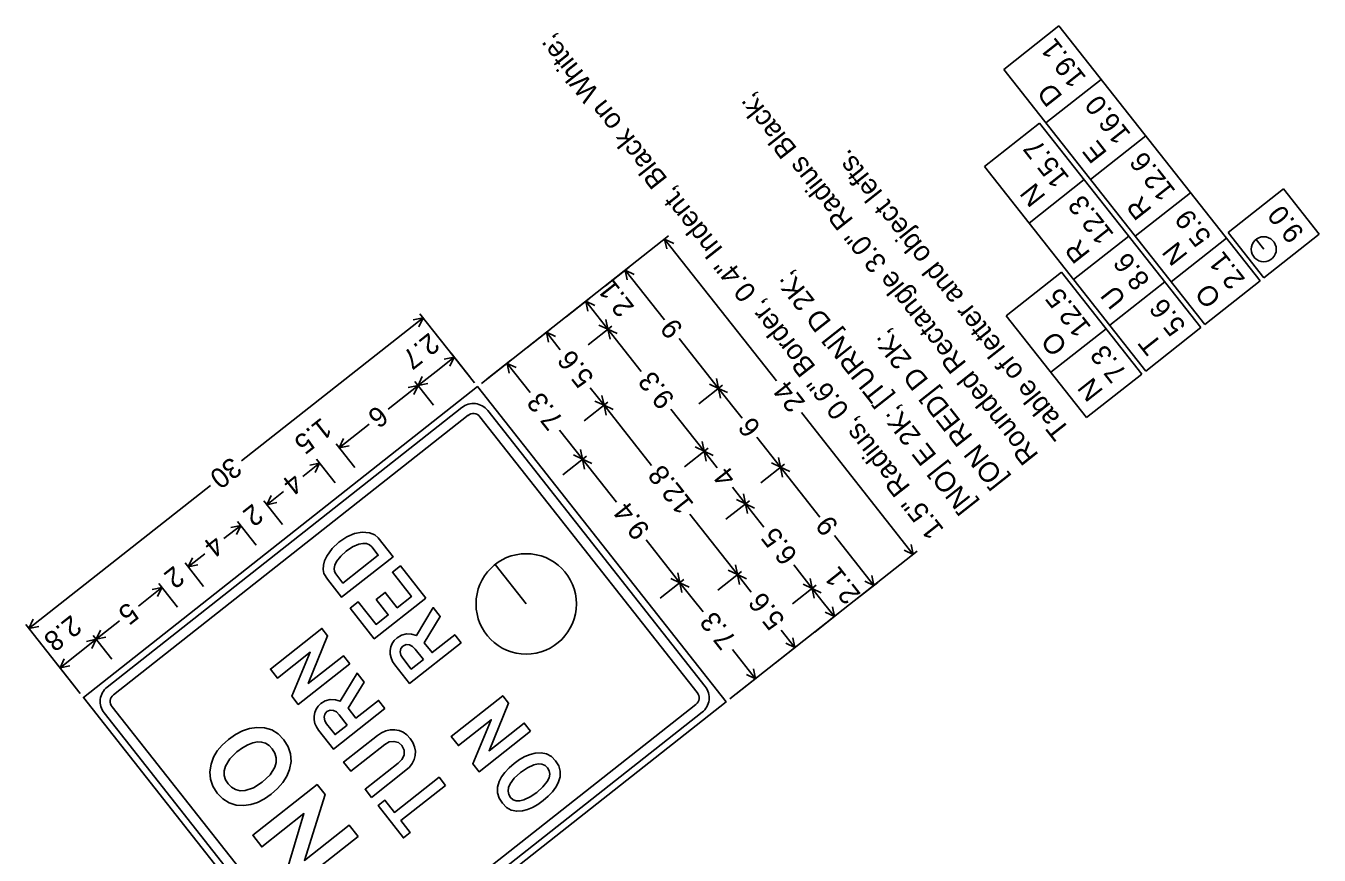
# Model space of a CAD drawing. Extents: x 672239 to 673995, y 1673540 to 1675195.
# Drawn here: x 672638.7 to 672697.6, y 1674762.7 to 1674800.5 of the extents above; entities that cross this region are included whole.
import ezdxf

# ---------------------------------------------------------------- set-up
doc = ezdxf.new("R2010")
doc.units = 0
doc.layers.add('C-ALGN-LINE', color=7, linetype='Continuous')

msp = doc.modelspace()

# ---------------------------------------------------------------- linework, layer by layer
at = {"layer": 'C-ALGN-LINE'}
for p, q in [((672683.213, 1674798.474), (672685.726, 1674800.455)), ((672685.726, 1674800.455), (672694.885, 1674788.838)), ((672683.213, 1674798.474), (672692.371, 1674786.856)), ((672685.134, 1674796.037), (672687.647, 1674798.019)), ((672682.334, 1674794.05), (672684.847, 1674796.031)), ((672684.847, 1674796.031), (672692.192, 1674786.715)), ((672687.164, 1674793.462), (672689.677, 1674795.444)), ((672682.334, 1674794.05), (672689.679, 1674784.733)), ((672684.364, 1674791.475), (672686.878, 1674793.456)), ((672689.203, 1674790.875), (672691.716, 1674792.857)), ((672693.434, 1674791.047), (672695.948, 1674793.028)), ((672695.948, 1674793.028), (672697.578, 1674790.961)), ((672667.944, 1674790.887), (672659.417, 1674784.164)), ((672672.861, 1674784.281), (672667.765, 1674790.745)), ((672668.179, 1674790.55), (672667.765, 1674790.745)), ((672667.857, 1674790.297), (672667.765, 1674790.745)), ((672686.395, 1674788.899), (672688.908, 1674790.88)), ((672690.839, 1674788.8), (672693.353, 1674790.781)), ((672693.434, 1674791.047), (672695.064, 1674788.979)), ((672694.702, 1674790.731), (672695.056, 1674790.282)), ((672695.056, 1674790.282), (672694.702, 1674790.731)), ((672695.064, 1674788.979), (672697.578, 1674790.961)), ((672666.149, 1674789.471), (672665.072, 1674788.622)), ((672667.758, 1674787.061), (672665.969, 1674789.33)), ((672666.383, 1674789.135), (672665.969, 1674789.33)), ((672666.062, 1674788.882), (672665.969, 1674789.33)), ((672683.325, 1674787.254), (672685.839, 1674789.235)), ((672685.839, 1674789.235), (672689.499, 1674784.592)), ((672688.036, 1674786.817), (672690.55, 1674788.798)), ((672692.371, 1674786.856), (672694.885, 1674788.838)), ((672664.354, 1674788.056), (672663.277, 1674787.207)), ((672664.679, 1674787.274), (672664.174, 1674787.915)), ((672664.588, 1674787.72), (672664.174, 1674787.915)), ((672664.267, 1674787.467), (672664.174, 1674787.915)), ((672648.494, 1674780.647), (672656.761, 1674787.164)), ((672656.313, 1674787.071), (672656.761, 1674787.164)), ((672656.566, 1674786.751), (672656.761, 1674787.164)), ((672656.619, 1674787.344), (672659.096, 1674784.202)), ((672664.679, 1674787.274), (672665.184, 1674786.634)), ((672665.091, 1674787.082), (672665.184, 1674786.634)), ((672683.325, 1674787.254), (672686.986, 1674782.611)), ((672662.559, 1674786.641), (672661.481, 1674785.792)), ((672663.011, 1674785.698), (672662.379, 1674786.499)), ((672662.793, 1674786.304), (672662.379, 1674786.499)), ((672662.472, 1674786.052), (672662.379, 1674786.499)), ((672665.363, 1674786.776), (672664.286, 1674785.926)), ((672665.363, 1674786.776), (672664.286, 1674785.926)), ((672664.77, 1674786.829), (672665.184, 1674786.634)), ((672666.699, 1674784.712), (672665.184, 1674786.634)), ((672665.598, 1674786.439), (672665.184, 1674786.634)), ((672665.277, 1674786.186), (672665.184, 1674786.634)), ((672685.359, 1674784.675), (672687.872, 1674786.656)), ((672689.679, 1674784.733), (672692.192, 1674786.715)), ((672668.426, 1674786.213), (672670.215, 1674783.944)), ((672657.353, 1674784.72), (672658.176, 1674785.369)), ((672657.728, 1674785.276), (672658.176, 1674785.369)), ((672657.981, 1674784.955), (672658.176, 1674785.369)), ((672658.034, 1674785.549), (672658.884, 1674784.471)), ((672660.763, 1674785.226), (672659.686, 1674784.376)), ((672657.353, 1674784.72), (672656.53, 1674784.072)), ((672661.633, 1674783.753), (672660.584, 1674785.084)), ((672660.998, 1674784.889), (672660.584, 1674785.084)), ((672660.677, 1674784.636), (672660.584, 1674785.084)), ((672655.167, 1674782.997), (672656.53, 1674784.072)), ((672656.083, 1674783.979), (672656.53, 1674784.072)), ((672656.335, 1674783.658), (672656.53, 1674784.072)), ((672656.389, 1674784.251), (672657.238, 1674783.174)), ((672656.389, 1674784.251), (672657.238, 1674783.174)), ((672656.725, 1674784.485), (672656.53, 1674784.072)), ((672656.978, 1674784.165), (672656.53, 1674784.072)), ((672670.395, 1674784.086), (672669.318, 1674783.237)), ((672670.395, 1674784.086), (672669.318, 1674783.237)), ((672669.801, 1674784.139), (672670.215, 1674783.944)), ((672670.122, 1674784.392), (672670.215, 1674783.944)), ((672686.986, 1674782.611), (672689.499, 1674784.592)), ((672664.37, 1674783.974), (672665.002, 1674783.172)), ((672664.909, 1674783.62), (672665.002, 1674783.172)), ((672671.29, 1674782.58), (672670.215, 1674783.944)), ((672670.629, 1674783.749), (672670.215, 1674783.944)), ((672670.308, 1674783.496), (672670.215, 1674783.944)), ((672665.182, 1674783.314), (672664.104, 1674782.465)), ((672665.182, 1674783.314), (672664.104, 1674782.465)), ((672664.588, 1674783.367), (672665.002, 1674783.172)), ((672667.165, 1674780.429), (672665.002, 1674783.172)), ((672665.416, 1674782.977), (672665.002, 1674783.172)), ((672665.095, 1674782.724), (672665.002, 1674783.172)), ((672668.046, 1674783.003), (672669.562, 1674781.081)), ((672673.991, 1674782.847), (672679.087, 1674776.383)), ((672654.304, 1674782.316), (672652.94, 1674781.241)), ((672662.978, 1674782.047), (672664.028, 1674780.716)), ((672671.971, 1674781.718), (672673.046, 1674780.354)), ((672652.798, 1674781.421), (672653.648, 1674780.344)), ((672653.135, 1674781.655), (672652.94, 1674781.241)), ((672653.388, 1674781.334), (672652.94, 1674781.241)), ((672663.935, 1674781.164), (672664.028, 1674780.716)), ((672669.741, 1674781.222), (672668.664, 1674780.373)), ((672669.148, 1674781.276), (672669.562, 1674781.081)), ((672669.469, 1674781.529), (672669.562, 1674781.081)), ((672670.161, 1674780.321), (672669.562, 1674781.081)), ((672669.976, 1674780.886), (672669.562, 1674781.081)), ((672669.654, 1674780.633), (672669.562, 1674781.081)), ((672651.282, 1674779.934), (672652.042, 1674780.534)), ((672651.595, 1674780.441), (672652.042, 1674780.534)), ((672651.847, 1674780.12), (672652.042, 1674780.534)), ((672651.901, 1674780.713), (672652.75, 1674779.636)), ((672664.207, 1674780.857), (672663.13, 1674780.008)), ((672664.207, 1674780.857), (672663.13, 1674780.008)), ((672663.614, 1674780.911), (672664.028, 1674780.716)), ((672665.571, 1674778.758), (672664.028, 1674780.716)), ((672664.441, 1674780.521), (672664.028, 1674780.716)), ((672664.121, 1674780.268), (672664.028, 1674780.716)), ((672673.225, 1674780.495), (672672.148, 1674779.646)), ((672672.632, 1674780.549), (672673.046, 1674780.354)), ((672672.953, 1674780.802), (672673.046, 1674780.354)), ((672674.835, 1674778.085), (672673.046, 1674780.354)), ((672673.46, 1674780.159), (672673.046, 1674780.354)), ((672673.139, 1674779.906), (672673.046, 1674780.354)), ((672647.075, 1674779.528), (672638.808, 1674773.012)), ((672670.85, 1674779.447), (672671.449, 1674778.687)), ((672649.507, 1674778.826), (672650.356, 1674777.749)), ((672650.409, 1674779.246), (672649.649, 1674778.647)), ((672649.844, 1674779.06), (672649.649, 1674778.647)), ((672650.096, 1674778.74), (672649.649, 1674778.647)), ((672671.628, 1674778.829), (672670.551, 1674777.98)), ((672671.035, 1674778.882), (672671.449, 1674778.687)), ((672671.356, 1674779.135), (672671.449, 1674778.687)), ((672668.915, 1674778.208), (672671.078, 1674775.465)), ((672672.29, 1674777.62), (672671.449, 1674778.687)), ((672671.863, 1674778.492), (672671.449, 1674778.687)), ((672671.542, 1674778.239), (672671.449, 1674778.687)), ((672647.692, 1674777.104), (672648.452, 1674777.703)), ((672648.004, 1674777.61), (672648.452, 1674777.703)), ((672648.257, 1674777.289), (672648.452, 1674777.703)), ((672648.31, 1674777.883), (672649.159, 1674776.805)), ((672666.919, 1674777.049), (672668.462, 1674775.091)), ((672675.503, 1674777.237), (672677.292, 1674774.968)), ((672646.818, 1674776.415), (672646.058, 1674775.816)), ((672679.266, 1674776.525), (672670.739, 1674769.802)), ((672678.673, 1674776.578), (672679.087, 1674776.383)), ((672678.994, 1674776.831), (672679.087, 1674776.383)), ((672645.917, 1674775.996), (672646.766, 1674774.918)), ((672646.253, 1674776.23), (672646.058, 1674775.816)), ((672646.506, 1674775.909), (672646.058, 1674775.816)), ((672660.042, 1674775.924), (672661.458, 1674774.129)), ((672661.458, 1674774.129), (672660.042, 1674775.924)), ((672670.985, 1674775.913), (672671.078, 1674775.465)), ((672673.646, 1674775.9), (672674.487, 1674774.833)), ((672668.642, 1674775.232), (672667.565, 1674774.383)), ((672668.048, 1674775.286), (672668.462, 1674775.091)), ((672668.369, 1674775.539), (672668.462, 1674775.091)), ((672671.258, 1674775.606), (672670.181, 1674774.757)), ((672670.665, 1674775.66), (672671.078, 1674775.465)), ((672671.71, 1674774.663), (672671.078, 1674775.465)), ((672671.492, 1674775.27), (672671.078, 1674775.465)), ((672671.171, 1674775.017), (672671.078, 1674775.465)), ((672674.394, 1674775.281), (672674.487, 1674774.833)), ((672677.199, 1674775.416), (672677.292, 1674774.968)), ((672643.791, 1674774.029), (672644.861, 1674774.873)), ((672644.414, 1674774.78), (672644.861, 1674774.873)), ((672644.666, 1674774.459), (672644.861, 1674774.873)), ((672644.72, 1674775.052), (672645.569, 1674773.975)), ((672669.512, 1674773.759), (672668.462, 1674775.091)), ((672668.876, 1674774.896), (672668.462, 1674775.091)), ((672668.555, 1674774.643), (672668.462, 1674775.091)), ((672674.666, 1674774.975), (672673.589, 1674774.126)), ((672674.073, 1674775.028), (672674.487, 1674774.833)), ((672674.992, 1674774.193), (672674.487, 1674774.833)), ((672674.901, 1674774.639), (672674.487, 1674774.833)), ((672674.58, 1674774.386), (672674.487, 1674774.833)), ((672677.471, 1674775.11), (672676.394, 1674774.261)), ((672676.878, 1674775.163), (672677.292, 1674774.968)), ((672674.992, 1674774.193), (672675.496, 1674773.553)), ((672675.404, 1674774.001), (672675.496, 1674773.553)), ((672639.003, 1674773.425), (672638.808, 1674773.012)), ((672675.676, 1674773.694), (672674.599, 1674772.845)), ((672675.083, 1674773.748), (672675.496, 1674773.553)), ((672638.667, 1674773.191), (672641.144, 1674770.05)), ((672639.256, 1674773.105), (672638.808, 1674773.012)), ((672642.939, 1674773.357), (672641.869, 1674772.514)), ((672642.064, 1674772.927), (672641.869, 1674772.514)), ((672673.069, 1674772.939), (672673.701, 1674772.138)), ((672641.047, 1674771.865), (672641.869, 1674772.514)), ((672641.422, 1674772.421), (672641.869, 1674772.514)), ((672641.674, 1674772.1), (672641.869, 1674772.514)), ((672641.728, 1674772.693), (672642.577, 1674771.616)), ((672642.317, 1674772.607), (672641.869, 1674772.514)), ((672673.881, 1674772.279), (672672.804, 1674771.43)), ((672673.287, 1674772.333), (672673.701, 1674772.138)), ((672673.608, 1674772.585), (672673.701, 1674772.138)), ((672641.047, 1674771.865), (672640.224, 1674771.216)), ((672670.856, 1674772.054), (672671.906, 1674770.722)), ((672640.082, 1674771.396), (672640.931, 1674770.319)), ((672640.419, 1674771.63), (672640.224, 1674771.216)), ((672640.672, 1674771.309), (672640.224, 1674771.216)), ((672671.813, 1674771.17), (672671.906, 1674770.722)), ((672672.085, 1674770.864), (672671.008, 1674770.015)), ((672671.492, 1674770.917), (672671.906, 1674770.722))]:
    msp.add_line(p, q, dxfattribs=at)
for points in [[(672670.56, 1674769.661), (672659.237, 1674784.023), (672641.285, 1674769.87), (672652.607, 1674755.508), (672670.56, 1674769.661), (672670.56, 1674769.661)], [(672642.372, 1674770.338), (672658.528, 1674783.076)], [(672659.706, 1674782.936), (672669.613, 1674770.37)], [(672658.812, 1674782.717), (672642.655, 1674769.979)], [(672669.253, 1674770.087), (672659.347, 1674782.653)], [(672652.4, 1674775.252), (672653.049, 1674774.428), (672655.396, 1674776.279), (672654.717, 1674777.14), (672654.558, 1674777.27), (672654.317, 1674777.358), (672653.982, 1674777.39), (672653.637, 1674777.331), (672653.284, 1674777.18), (672652.924, 1674776.939), (672652.618, 1674776.649), (672652.377, 1674776.309), (672652.275, 1674776.092), (672652.218, 1674775.887), (672652.209, 1674775.695), (672652.246, 1674775.514), (672652.4, 1674775.252)], [(672654.42, 1674776.724), (672654.72, 1674776.343), (672653.111, 1674775.074), (672652.783, 1674775.49), (672652.719, 1674775.61), (672652.704, 1674775.747), (672652.739, 1674775.898), (672652.821, 1674776.064), (672653.009, 1674776.306), (672653.262, 1674776.537), (672653.552, 1674776.729), (672653.841, 1674776.85), (672654.024, 1674776.885), (672654.181, 1674776.876), (672654.313, 1674776.822), (672654.42, 1674776.724)], [(672658.491, 1674772.353), (672658.201, 1674772.722), (672657.171, 1674771.91), (672656.817, 1674772.359), (672657.545, 1674773.554), (672657.222, 1674773.963), (672656.457, 1674772.681), (672656.237, 1674772.751), (672656.002, 1674772.757), (672655.775, 1674772.701), (672655.576, 1674772.585), (672655.448, 1674772.462), (672655.353, 1674772.324), (672655.291, 1674772.172), (672655.261, 1674772.004), (672655.265, 1674771.833), (672655.302, 1674771.667), (672655.37, 1674771.509), (672655.47, 1674771.357), (672656.146, 1674770.504), (672658.491, 1674772.353)], [(672656.774, 1674771.597), (672656.222, 1674771.161), (672655.836, 1674771.651), (672655.752, 1674771.795), (672655.722, 1674771.949), (672655.752, 1674772.093), (672655.846, 1674772.209), (672655.989, 1674772.276), (672656.145, 1674772.264), (672656.284, 1674772.192), (672656.403, 1674772.067), (672656.774, 1674771.597)], [(672655.023, 1674769.367), (672654.733, 1674769.735), (672653.703, 1674768.924), (672653.349, 1674769.373), (672654.077, 1674770.568), (672653.755, 1674770.977), (672652.989, 1674769.695), (672652.769, 1674769.765), (672652.534, 1674769.771), (672652.308, 1674769.715), (672652.108, 1674769.598), (672651.98, 1674769.476), (672651.885, 1674769.338), (672651.823, 1674769.186), (672651.793, 1674769.018), (672651.798, 1674768.846), (672651.834, 1674768.681), (672651.902, 1674768.523), (672652.002, 1674768.371), (672652.678, 1674767.518), (672655.023, 1674769.367)], [(672642.591, 1674769.444), (672652.498, 1674756.878)], [(672653.306, 1674768.611), (672652.754, 1674768.175), (672652.368, 1674768.665), (672652.284, 1674768.809), (672652.254, 1674768.962), (672652.284, 1674769.107), (672652.378, 1674769.223), (672652.521, 1674769.29), (672652.677, 1674769.278), (672652.816, 1674769.206), (672652.936, 1674769.081), (672653.306, 1674768.611)], [(672653.033, 1674756.814), (672669.19, 1674769.552)], [(672652.139, 1674756.595), (672642.232, 1674769.161)], [(672669.473, 1674769.193), (672653.316, 1674756.455)], [(672647.899, 1674767.956), (672647.616, 1674767.701), (672647.388, 1674767.429), (672647.219, 1674767.14), (672647.103, 1674766.834), (672647.047, 1674766.486), (672647.076, 1674766.15), (672647.19, 1674765.826), (672647.388, 1674765.514), (672647.644, 1674765.251), (672647.929, 1674765.067), (672648.245, 1674764.965), (672648.59, 1674764.941), (672648.908, 1674764.984), (672649.221, 1674765.084), (672649.534, 1674765.243), (672649.844, 1674765.459), (672650.136, 1674765.718), (672650.372, 1674765.993), (672650.553, 1674766.284), (672650.68, 1674766.592), (672650.749, 1674766.951), (672650.729, 1674767.295), (672650.619, 1674767.625), (672650.419, 1674767.941), (672650.161, 1674768.205), (672649.869, 1674768.388), (672649.543, 1674768.487), (672649.183, 1674768.503), (672648.86, 1674768.451), (672648.537, 1674768.342), (672648.218, 1674768.178), (672647.899, 1674767.956)], [(672648.279, 1674767.391), (672648.537, 1674767.576), (672648.779, 1674767.713), (672649.005, 1674767.801), (672649.212, 1674767.843), (672649.407, 1674767.835), (672649.584, 1674767.78), (672649.746, 1674767.676), (672649.891, 1674767.525), (672650.014, 1674767.327), (672650.074, 1674767.122), (672650.071, 1674766.91), (672650.004, 1674766.689), (672649.788, 1674766.338), (672649.437, 1674766.001), (672649.039, 1674765.748), (672648.652, 1674765.627), (672648.425, 1674765.62), (672648.22, 1674765.67), (672648.037, 1674765.775), (672647.876, 1674765.936), (672647.762, 1674766.121), (672647.704, 1674766.317), (672647.703, 1674766.52), (672647.758, 1674766.731), (672647.956, 1674767.074), (672648.279, 1674767.391)], [(672660.916, 1674766.86), (672660.68, 1674766.656), (672660.486, 1674766.451), (672660.335, 1674766.246), (672660.226, 1674766.04), (672660.152, 1674765.781), (672660.151, 1674765.528), (672660.225, 1674765.283), (672660.371, 1674765.045), (672660.563, 1674764.855), (672660.78, 1674764.734), (672661.024, 1674764.683), (672661.295, 1674764.702), (672661.52, 1674764.761), (672661.749, 1674764.858), (672661.985, 1674764.994), (672662.225, 1674765.167), (672662.459, 1674765.368), (672662.652, 1674765.57), (672662.805, 1674765.774), (672662.917, 1674765.981), (672663.003, 1674766.246), (672663.011, 1674766.502), (672662.942, 1674766.749), (672662.796, 1674766.987), (672662.605, 1674767.177), (672662.386, 1674767.298), (672662.137, 1674767.35), (672661.86, 1674767.332), (672661.632, 1674767.271), (672661.398, 1674767.171), (672661.16, 1674767.035), (672660.916, 1674766.86)], [(672661.198, 1674766.447), (672661.517, 1674766.664), (672661.812, 1674766.797), (672662.005, 1674766.836), (672662.173, 1674766.825), (672662.317, 1674766.764), (672662.435, 1674766.655), (672662.51, 1674766.519), (672662.531, 1674766.371), (672662.498, 1674766.21), (672662.411, 1674766.037), (672662.218, 1674765.789), (672661.942, 1674765.541), (672661.641, 1674765.335), (672661.354, 1674765.203), (672661.162, 1674765.156), (672660.997, 1674765.158), (672660.859, 1674765.21), (672660.748, 1674765.309), (672660.666, 1674765.452), (672660.634, 1674765.604), (672660.656, 1674765.766), (672660.728, 1674765.938), (672660.916, 1674766.19), (672661.198, 1674766.447)]]:
    msp.add_lwpolyline(points, dxfattribs=at)
for points in [[(672656.887, 1674774.388), (672655.73, 1674775.856), (672655.362, 1674775.566), (672656.232, 1674774.462), (672655.587, 1674773.954), (672655.039, 1674774.65), (672654.624, 1674774.324), (672655.173, 1674773.628), (672654.62, 1674773.192), (672653.811, 1674774.219), (672653.443, 1674773.929), (672654.54, 1674772.537)], [(672653.419, 1674771.402), (672653.129, 1674771.77), (672651.527, 1674770.507), (672652.414, 1674772.678), (672652.151, 1674773.011), (672649.803, 1674771.161), (672650.128, 1674770.748), (672651.622, 1674771.925), (672650.782, 1674769.919), (672651.072, 1674769.551)], [(672661.661, 1674768.332), (672661.371, 1674768.7), (672659.769, 1674767.437), (672660.656, 1674769.608), (672660.393, 1674769.941), (672658.045, 1674768.091), (672658.37, 1674767.678), (672659.863, 1674768.855), (672659.024, 1674766.85), (672659.314, 1674766.481)], [(672654.412, 1674765.315), (672655.981, 1674766.551), (672656.141, 1674766.699), (672656.263, 1674766.861), (672656.35, 1674767.037), (672656.398, 1674767.225), (672656.411, 1674767.427), (672656.377, 1674767.623), (672656.299, 1674767.814), (672656.177, 1674767.999), (672656.025, 1674768.16), (672655.855, 1674768.28), (672655.667, 1674768.359), (672655.461, 1674768.394), (672655.257, 1674768.389), (672655.059, 1674768.345), (672654.868, 1674768.26), (672654.681, 1674768.136), (672653.143, 1674766.924), (672653.468, 1674766.511), (672655.011, 1674767.727), (672655.212, 1674767.838), (672655.429, 1674767.866), (672655.636, 1674767.811), (672655.8, 1674767.671), (672655.902, 1674767.465), (672655.893, 1674767.244), (672655.799, 1674767.046), (672655.627, 1674766.869), (672654.122, 1674765.683)], [(672653.801, 1674763.533), (672653.393, 1674764.05), (672651.354, 1674762.443), (672652.294, 1674765.445), (672651.935, 1674765.9), (672649.001, 1674763.587), (672649.415, 1674763.061), (672651.335, 1674764.574), (672650.472, 1674761.72), (672650.867, 1674761.219)], [(672657.787, 1674765.861), (672657.492, 1674766.235), (672655.456, 1674764.63), (672655.019, 1674765.185), (672654.708, 1674764.939), (672655.865, 1674763.471), (672656.176, 1674763.717), (672655.751, 1674764.256)]]:
    msp.add_lwpolyline(points, close=True, dxfattribs=at)
for centre, radius in [((672695.056, 1674790.282), 0.571), ((672661.458, 1674774.129), 2.286)]:
    msp.add_circle(centre, radius, dxfattribs=at)
for centre, radius, start, end in [((672659.047, 1674782.417), 0.838, 38.2506, 128.25081), ((672659.047, 1674782.417), 0.381, 38.2506, 128.25081), ((672642.89, 1674769.68), 0.838, 128.25054, 218.25075), ((672642.89, 1674769.68), 0.381, 128.25054, 218.25075), ((672668.954, 1674769.851), 0.381, 308.25039, 38.2506), ((672668.954, 1674769.851), 0.838, 308.25039, 38.2506)]:
    msp.add_arc(centre, radius, start, end, dxfattribs=at)

# ---------------------------------------------------------------- texts
for s, height, rotation, p in [('1.5" Radius, 0.6" Border, 0.4" Indent, Black on White; ', 0.9144, 128.25054, (672680.523, 1674777.516)), ('19.1', 0.9144, 128.25054, (672687.005, 1674798.095)), ('D', 0.914, 128.25054, (672685.928, 1674797.245)), ('Rounded Rectangle 3.0" Radius Black; ', 0.9144, 128.25054, (672684.832, 1674780.912)), ('16.0', 0.9144, 128.25054, (672689.035, 1674795.52)), ('E', 0.914, 128.25054, (672687.958, 1674794.67)), ('Table of letter and object lefts.', 0.9144, 128.25054, (672686.268, 1674782.044)), ('15.7', 0.9144, 128.25054, (672686.236, 1674793.532)), ('12.6', 0.9144, 128.25054, (672691.074, 1674792.933)), ('N', 0.914, 128.25054, (672685.158, 1674792.683)), ('12.3', 0.9144, 128.25054, (672688.266, 1674790.956)), ('R', 0.914, 128.25054, (672689.997, 1674792.083)), ('5.9', 0.9144, 128.25054, (672692.71, 1674790.857)), ('9.0', 0.9144, 128.25054, (672696.936, 1674791.037)), ('R', 0.914, 128.25054, (672687.189, 1674790.107)), ('N', 0.914, 128.25054, (672691.633, 1674790.008)), ('8.6', 0.9144, 128.25054, (672689.908, 1674788.874)), ('2.1', 0.9144, 128.25054, (672694.243, 1674788.914)), ('[NO] E 2K; [TURN] D 2K; ', 0.9144, 128.25054, (672681.959, 1674778.648)), ('2.1', 0.9144, 128.25054, (672666.419, 1674787.652)), ('12.5', 0.9144, 128.25054, (672687.23, 1674786.732)), ('U', 0.914, 128.25054, (672688.831, 1674788.025)), ('O', 0.914, 128.25054, (672693.166, 1674788.065)), ('5.6', 0.9144, 128.25054, (672691.55, 1674786.791)), ('9', 0.914, 128.25054, (672668.644, 1674786.676)), ('2.7', 0.9144, 218.25075, (672657.045, 1674786.515)), ('[ON RED] D 2K; ', 0.9144, 128.25054, (672683.395, 1674779.78)), ('O', 0.914, 128.25054, (672686.153, 1674785.883)), ('7.3', 0.9144, 128.25054, (672688.857, 1674784.668)), ('T', 0.914, 128.25054, (672690.473, 1674785.942)), ('5.6', 0.9144, 128.25054, (672664.587, 1674784.437)), ('9.3', 0.9144, 128.25054, (672668.264, 1674783.466)), ('24', 0.9144, 128.25054, (672674.208, 1674783.31)), ('N', 0.914, 128.25054, (672687.78, 1674783.819)), ('7.3', 0.9144, 128.25054, (672663.195, 1674782.51)), ('6', 0.914, 218.25075, (672654.704, 1674783.214)), ('1.5', 0.9144, 218.25075, (672652.143, 1674782.651)), ('6', 0.914, 128.25054, (672672.188, 1674782.18)), ('30', 0.9144, 218.25075, (672648.032, 1674780.865)), ('4', 0.914, 218.25075, (672650.82, 1674780.152)), ('12.8', 0.9144, 128.25054, (672669.133, 1674778.671)), ('4', 0.914, 128.25054, (672671.067, 1674779.91)), ('9.4', 0.9144, 128.25054, (672667.136, 1674777.511)), ('2', 0.914, 218.25075, (672649.014, 1674778.728)), ('6.5', 0.9144, 128.25054, (672673.863, 1674776.363)), ('9', 0.914, 128.25054, (672675.72, 1674777.7)), ('4', 0.914, 218.25075, (672647.229, 1674777.321)), ('2', 0.914, 218.25075, (672645.423, 1674775.898)), ('2.1', 0.9144, 128.25054, (672676.731, 1674774.571)), ('5.6', 0.9144, 128.25054, (672673.287, 1674773.402)), ('5', 0.914, 218.25075, (672643.329, 1674774.247)), ('2.8', 0.9144, 218.25075, (672640.74, 1674773.661)), ('7.3', 0.9144, 128.25054, (672671.074, 1674772.516))]:
    msp.add_text(s, height=height, rotation=rotation, dxfattribs=at).set_placement(p)

doc.saveas('drawing.dxf')
